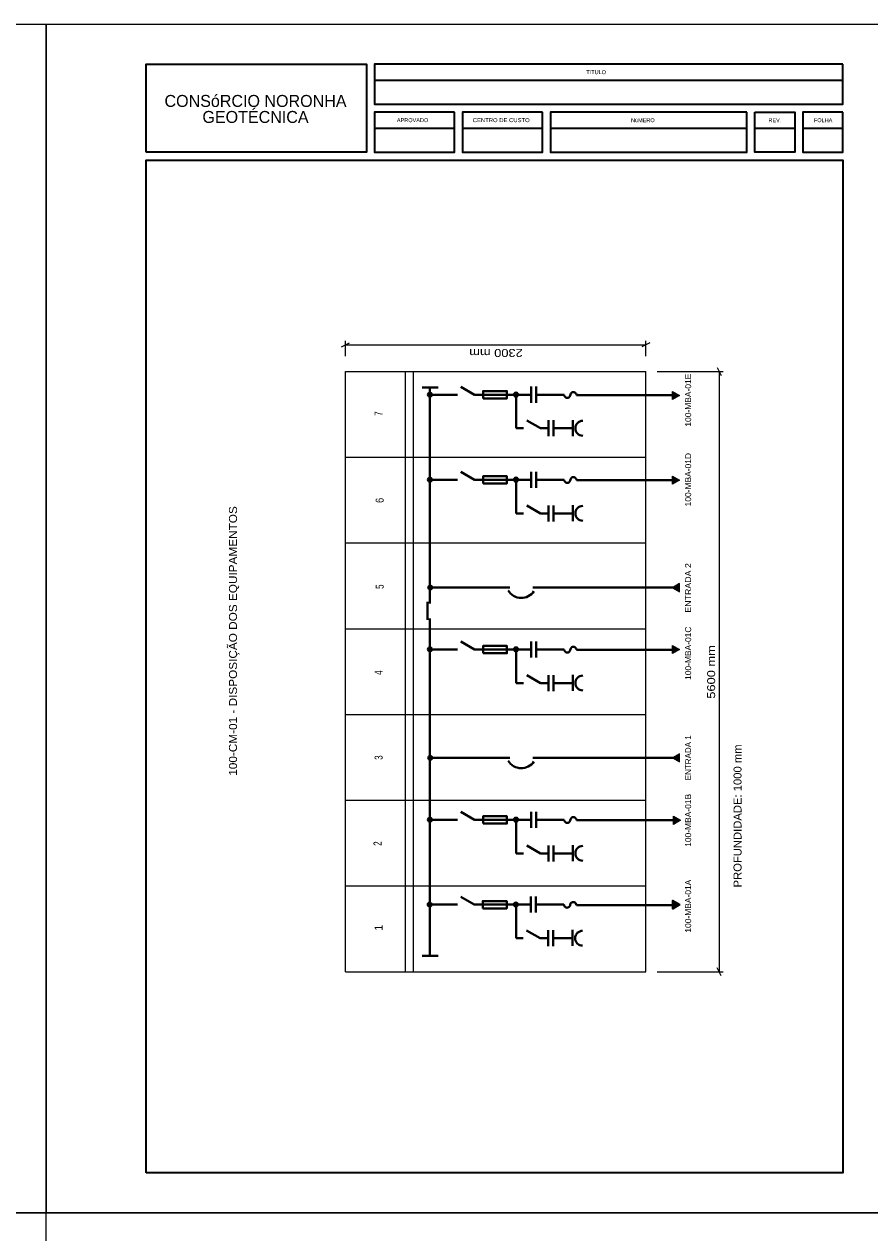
# Model space of a CAD drawing. Extents: x -4160 to -2690, y -474 to 714.
# Drawn here: x -3115.3 to -2904, y 412.5 to 714.5 of the extents above; entities that cross this region are included whole.
import ezdxf
from ezdxf.enums import TextEntityAlignment as Align

# ---------------------------------------------------------------- set-up
doc = ezdxf.new("R2010")
doc.units = 0
doc.header["$LTSCALE"] = 0.56
doc.layers.add('5', color=7, linetype='Continuous', lineweight=35)

msp = doc.modelspace()

# ---------------------------------------------------------------- hatches: boundary and pattern name
at = {"layer": '5'}
for points in [[(-3013.9181, 622.4181, 1), (-3013.9181, 621.4181, 1)], [(-2992.4004, 622.4181, 1), (-2992.4004, 621.4181, 1)], [(-2951.5592, 621.706), (-2953.3121, 620.694), (-2953.3121, 622.718)], [(-3013.9181, 601.1728, 1), (-3013.9181, 600.1728, 1)], [(-2992.4004, 601.1728, 1), (-2992.4004, 600.1728, 1)], [(-2951.5592, 600.5456), (-2953.3121, 599.5336), (-2953.3121, 601.5576)], [(-3013.8436, 574.2158, 1), (-3013.8436, 573.2158, 1)], [(-2953.3234, 573.6788), (-2951.5705, 572.6668), (-2951.5705, 574.6908)], [(-3013.9181, 558.7673, 1), (-3013.9181, 557.7673, 1)], [(-2992.4004, 558.7673, 1), (-2992.4004, 557.7673, 1)], [(-2951.5593, 558.2133), (-2953.3122, 557.2013), (-2953.3122, 559.2253)], [(-3013.8436, 531.6615, 1), (-3013.8436, 530.6615, 1)], [(-2953.315, 531.1744), (-2951.5621, 530.1624), (-2951.5621, 532.1864)], [(-2951.3339, 515.5545), (-2953.0868, 514.5425), (-2953.0868, 516.5665)], [(-3013.9181, 516.213, 1), (-3013.9181, 515.213, 1)], [(-3013.9181, 516.2094, 1), (-3013.9181, 515.2166, 1)], [(-2992.4004, 516.213, 1), (-2992.4004, 515.213, 1)], [(-2951.4563, 494.4858), (-2953.2092, 493.4738), (-2953.2092, 495.4978)], [(-3013.9648, 495.0045, 1), (-3013.9648, 494.0045, 1)], [(-2992.4471, 495.0045, 1), (-2992.4471, 494.0045, 1)]]:
    msp.add_hatch(color=256, dxfattribs=at).paths.add_polyline_path(points)

# ---------------------------------------------------------------- linework, layer by layer
at = {"layer": '5', "lineweight": 25}
for p, q in [((-3109.7642, 417.48), (-3109.7642, 714.48)), ((-3109.7642, 714.48), (-3109.7642, 417.48)), ((-3035.9935, 633.8299), (-3033.9935, 634.8299)), ((-3034.9935, 631.5442), (-3034.9935, 635.3299)), ((-3034.9935, 634.3299), (-2959.9935, 634.3299)), ((-2958.9935, 634.8299), (-2960.9935, 633.8299)), ((-2959.9935, 631.5442), (-2959.9935, 635.3299)), ((-2942.1569, 628.7154), (-2941.1569, 626.7154)), ((-3034.9935, 477.7154), (-3034.9935, 627.7154)), ((-3034.9935, 627.7154), (-2959.9935, 627.7154)), ((-3019.9935, 477.7154), (-3019.9935, 627.7154)), ((-3017.9935, 477.7154), (-3017.9935, 627.7154)), ((-2959.9935, 477.7154), (-2959.9935, 627.7154)), ((-2957.1397, 627.7154), (-2940.6569, 627.7154)), ((-2941.6569, 627.7154), (-2941.6569, 477.7154)), ((-3034.9935, 606.2868), (-2959.9935, 606.2868)), ((-3034.9935, 584.8582), (-2959.9935, 584.8582)), ((-3034.9935, 563.4296), (-2959.9935, 563.4296)), ((-3034.9935, 542.0011), (-2959.9935, 542.0011)), ((-3034.9935, 520.5725), (-2959.9935, 520.5725)), ((-3034.9935, 499.1439), (-2959.9935, 499.1439)), ((-3034.9935, 477.7154), (-2959.9935, 477.7154)), ((-2957.1397, 477.7154), (-2940.6569, 477.7154)), ((-2941.1569, 476.7154), (-2942.1569, 478.7154)), ((-3319.7642, 417.48), (-3109.7642, 417.48))]:
    msp.add_line(p, q, dxfattribs=at)
at = {"layer": '5'}
for p, q in [((-3027.7642, 700.48), (-2910.7642, 700.48)), ((-3027.7642, 688.48), (-3007.7642, 688.48)), ((-3005.7642, 688.48), (-2985.7642, 688.48)), ((-2983.7642, 688.48), (-2934.7642, 688.48)), ((-2932.7642, 688.48), (-2922.7642, 688.48)), ((-2920.7642, 688.48), (-2910.7642, 688.48))]:
    msp.add_line(p, q, dxfattribs=at)
at = {"layer": '5', "lineweight": 40}
for p, q in [((-3015.8797, 623.7284), (-3011.8797, 623.7284)), ((-3013.9648, 569.7636), (-3013.9648, 623.738)), ((-3002.7726, 621.9058), (-3006.1501, 623.8558)), ((-2988.6427, 619.9065), (-2988.6427, 623.9065)), ((-2987.3789, 619.9065), (-2987.3789, 623.9065)), ((-3013.9803, 621.9058), (-3006.9803, 621.9058)), ((-3002.7726, 621.9058), (-2988.6427, 621.9058)), ((-2987.3789, 621.9065), (-2980.3789, 621.9065)), ((-2977.2827, 621.7691), (-2952.982, 621.7691)), ((-2992.3273, 613.4991), (-2990.5269, 613.4991)), ((-2986.3192, 613.4991), (-2989.6967, 615.4491)), ((-2986.3192, 613.4991), (-2984.3242, 613.4991)), ((-2986.3192, 613.4991), (-2984.7328, 613.4991)), ((-2984.3242, 611.4998), (-2984.3242, 615.4998)), ((-2983.0604, 611.4998), (-2983.0604, 615.4998)), ((-2983.0604, 613.4998), (-2978.3525, 613.4998)), ((-2978.2189, 611.5742), (-2978.2189, 615.5742)), ((-3002.7726, 600.6605), (-3006.1501, 602.6105)), ((-2988.6427, 598.6612), (-2988.6427, 602.6612)), ((-2987.3789, 598.6612), (-2987.3789, 602.6612)), ((-3013.9803, 600.6605), (-3006.9803, 600.6605)), ((-3002.7726, 600.6605), (-2988.6427, 600.6605)), ((-2987.3789, 600.6612), (-2980.3789, 600.6612)), ((-2977.2827, 600.5238), (-2952.2827, 600.5238)), ((-2992.3273, 592.2538), (-2990.5269, 592.2538)), ((-2986.3192, 592.2538), (-2989.6967, 594.2038)), ((-2986.3192, 592.2538), (-2984.3242, 592.2538)), ((-2986.3192, 592.2538), (-2984.7328, 592.2538)), ((-2984.3242, 590.2545), (-2984.3242, 594.2545)), ((-2983.0604, 590.2545), (-2983.0604, 594.2545)), ((-2983.0604, 592.2545), (-2978.3525, 592.2545)), ((-2978.2189, 590.3289), (-2978.2189, 594.3289)), ((-3013.9648, 573.6975), (-2993.9648, 573.6975)), ((-2988.2031, 573.6975), (-2952.4454, 573.6975)), ((-3014.5203, 565.6803), (-3014.5203, 570.1204)), ((-3013.9648, 481.738), (-3013.9648, 565.9975)), ((-3002.7726, 558.255), (-3006.1501, 560.205)), ((-2988.6427, 556.2557), (-2988.6427, 560.2557)), ((-2987.3789, 556.2557), (-2987.3789, 560.2557)), ((-3013.9803, 558.255), (-3006.9803, 558.255)), ((-3002.7726, 558.255), (-2988.6427, 558.255)), ((-2987.3789, 558.2557), (-2980.3789, 558.2557)), ((-2977.2827, 558.1183), (-2952.2827, 558.1183)), ((-2992.3273, 549.8483), (-2990.5269, 549.8483)), ((-2986.3192, 549.8483), (-2989.6967, 551.7983)), ((-2986.3192, 549.8483), (-2984.3242, 549.8483)), ((-2986.3192, 549.8483), (-2984.7328, 549.8483)), ((-2984.3242, 547.849), (-2984.3242, 551.849)), ((-2983.0604, 547.849), (-2983.0604, 551.849)), ((-2983.0604, 549.849), (-2978.3525, 549.849)), ((-2978.2189, 547.9234), (-2978.2189, 551.9234)), ((-3013.9648, 531.1432), (-2993.9648, 531.1432)), ((-2988.2031, 531.1432), (-2952.4454, 531.1432)), ((-3002.7726, 515.7007), (-3006.1501, 517.6507)), ((-2988.6427, 513.7014), (-2988.6427, 517.7014)), ((-2987.3789, 513.7014), (-2987.3789, 517.7014)), ((-3013.9803, 515.7007), (-3006.9803, 515.7007)), ((-3002.7726, 515.7007), (-2988.6427, 515.7007)), ((-2987.3789, 515.7014), (-2980.3789, 515.7014)), ((-2977.2827, 515.564), (-2952.2827, 515.564)), ((-2986.3192, 507.294), (-2989.6967, 509.244)), ((-2984.3242, 505.2947), (-2984.3242, 509.2947)), ((-2983.0604, 505.2947), (-2983.0604, 509.2947)), ((-2978.2189, 505.3691), (-2978.2189, 509.3691)), ((-2992.3273, 507.294), (-2990.5269, 507.294)), ((-2986.3192, 507.294), (-2984.3242, 507.294)), ((-2986.3192, 507.294), (-2984.7328, 507.294)), ((-2983.0604, 507.2947), (-2978.3525, 507.2947)), ((-3002.8193, 494.4922), (-3006.1968, 496.4422)), ((-2988.6894, 492.4929), (-2988.6894, 496.4929)), ((-2987.4256, 492.4929), (-2987.4256, 496.4929)), ((-3014.027, 494.4922), (-3007.027, 494.4922)), ((-3002.8193, 494.4922), (-2988.6894, 494.4922)), ((-2987.4256, 494.4929), (-2980.4256, 494.4929)), ((-2977.3294, 494.3555), (-2952.3294, 494.3555)), ((-2986.3659, 486.0855), (-2989.7434, 488.0355)), ((-2984.3709, 484.0862), (-2984.3709, 488.0862)), ((-2983.1071, 484.0862), (-2983.1071, 488.0862)), ((-2978.2656, 484.1606), (-2978.2656, 488.1606)), ((-2992.374, 486.0855), (-2990.5736, 486.0855)), ((-2986.3659, 486.0855), (-2984.3709, 486.0855)), ((-2986.3659, 486.0855), (-2984.7795, 486.0855)), ((-2983.1071, 486.0862), (-2978.3992, 486.0862)), ((-3015.8126, 481.7044), (-3011.8126, 481.7044))]:
    msp.add_line(p, q, dxfattribs=at)
at = {"layer": '5', "lineweight": 25}
msp.add_lwpolyline([(-3109.7642, 417.48), (-3319.7642, 417.48), (-3319.7642, 714.48), (-3109.7642, 714.48)], dxfattribs=at)
for points in [[(-2899.7642, 417.48), (-3109.7642, 417.48), (-3109.7642, 714.48), (-2899.7642, 714.48)], [(-2951.5592, 621.706), (-2953.3121, 620.694), (-2953.3121, 622.718)], [(-2951.5592, 600.5456), (-2953.3121, 599.5336), (-2953.3121, 601.5576)], [(-2953.3234, 573.6788), (-2951.5705, 572.6668), (-2951.5705, 574.6908)], [(-2951.5593, 558.2133), (-2953.3122, 557.2013), (-2953.3122, 559.2253)], [(-2953.315, 531.1744), (-2951.5621, 530.1624), (-2951.5621, 532.1864)], [(-2951.3339, 515.5545), (-2953.0868, 514.5425), (-2953.0868, 516.5665)], [(-2899.7642, 120.48), (-3109.7642, 120.48), (-3109.7642, 417.48), (-2899.7642, 417.48)]]:
    msp.add_lwpolyline(points, close=True, dxfattribs=at)
at = {"layer": '5'}
for points in [[(-3084.7642, 682.48), (-3084.7642, 704.48), (-3029.7642, 704.48), (-3029.7642, 682.48)], [(-2910.7642, 704.48), (-3027.7642, 704.48), (-3027.7642, 694.48), (-2910.7642, 694.48)], [(-3007.7642, 692.48), (-3027.7642, 692.48), (-3027.7642, 682.48), (-3007.7642, 682.48)], [(-2985.7642, 692.48), (-3005.7642, 692.48), (-3005.7642, 682.48), (-2985.7642, 682.48)], [(-2934.7642, 692.48), (-2983.7642, 692.48), (-2983.7642, 682.48), (-2934.7642, 682.48)], [(-2932.7642, 692.48), (-2922.7642, 692.48), (-2922.7642, 682.48), (-2932.7642, 682.48)], [(-2910.7642, 692.48), (-2920.7642, 692.48), (-2920.7642, 682.48), (-2910.7642, 682.48)], [(-3084.7642, 427.48), (-3084.7642, 680.48), (-2910.7642, 680.48), (-2910.7642, 427.48)], [(-2951.4563, 494.4858), (-2953.2092, 493.4738), (-2953.2092, 495.4978)]]:
    msp.add_lwpolyline(points, close=True, dxfattribs=at)
at = {"layer": '5', "lineweight": 40}
for points in [[(-3000.6487, 620.9588), (-3000.6487, 622.7828), (-2994.6808, 622.7828), (-2994.6808, 620.9588)], [(-3000.6487, 599.7135), (-3000.6487, 601.5375), (-2994.6808, 601.5375), (-2994.6808, 599.7135)], [(-3000.6487, 557.308), (-3000.6487, 559.132), (-2994.6808, 559.132), (-2994.6808, 557.308)], [(-3000.6487, 514.7537), (-3000.6487, 516.5777), (-2994.6808, 516.5777), (-2994.6808, 514.7537)], [(-3000.6954, 493.5452), (-3000.6954, 495.3692), (-2994.7275, 495.3692), (-2994.7275, 493.5452)]]:
    msp.add_lwpolyline(points, close=True, dxfattribs=at)
for points in [[(-2992.3273, 613.4991), (-2992.3273, 621.9058), (-2992.3273, 621.9058), (-2992.3273, 621.9181)], [(-2992.3273, 592.2538), (-2992.3273, 600.6605), (-2992.3273, 600.6605), (-2992.3273, 600.6728)], [(-2992.3273, 549.8483), (-2992.3273, 558.255), (-2992.3273, 558.255), (-2992.3273, 558.2673)], [(-2992.3273, 507.294), (-2992.3273, 515.7007), (-2992.3273, 515.7007), (-2992.3273, 515.713)], [(-2992.374, 486.0855), (-2992.374, 494.4922), (-2992.374, 494.4922), (-2992.374, 494.5045)]]:
    msp.add_lwpolyline(points, dxfattribs=at)
for centre, radius in [((-3013.9181, 621.9181), 0.5), ((-2992.4004, 621.9181), 0.5), ((-3013.9181, 600.6728), 0.5), ((-2992.4004, 600.6728), 0.5), ((-3013.8436, 573.7158), 0.5), ((-3013.9181, 558.2673), 0.5), ((-2992.4004, 558.2673), 0.5), ((-3013.8436, 531.1615), 0.5), ((-3013.9181, 515.713), 0.5), ((-3013.9181, 515.713), 0.4964), ((-2992.4004, 515.713), 0.5), ((-3013.9648, 494.5045), 0.5), ((-2992.4471, 494.5045), 0.5)]:
    msp.add_circle(centre, radius, dxfattribs=at)
for centre, radius, start, end in [((-2978.0585, 621.7698), 0.7758, 359.9483, 180), ((-2979.6031, 621.9058), 0.7758, 179.9483, 0), ((-2975.7224, 613.5114), 1.8599, 90, 270), ((-2978.0585, 600.5245), 0.7758, 359.9483, 180), ((-2979.6031, 600.6605), 0.7758, 179.9483, 0), ((-2975.7224, 592.2661), 1.8599, 90, 270), ((-2991.069, 574.9606), 3.8414, 211.55542, 325.35427), ((-2978.0585, 558.119), 0.7758, 359.9483, 180), ((-2979.6031, 558.255), 0.7758, 179.9483, 0), ((-2975.7224, 549.8606), 1.8599, 90, 270), ((-2991.069, 532.4063), 3.8414, 211.55542, 325.35427), ((-2979.6031, 515.7007), 0.7758, 179.9483, 0), ((-2978.0585, 515.5647), 0.7758, 359.9483, 180), ((-2975.7224, 507.3063), 1.8599, 90, 270), ((-2979.6498, 494.4922), 0.7758, 179.9483, 0), ((-2978.1052, 494.3562), 0.7758, 359.9483, 180), ((-2975.7691, 486.0978), 1.8599, 90, 270)]:
    msp.add_arc(centre, radius, start, end, dxfattribs=at)

# ---------------------------------------------------------------- texts
at = {"layer": '5'}
for s, height, p in [('TíTULO', 1, (-2972.3847, 701.991)), ('CONSóRCIO NORONHA', 3, (-3057.4749, 693.7961)), ('GEOTÉCNICA', 3, (-3057.475, 689.7961)), ('APROVADO', 1, (-3018.2387, 689.9973)), ('REV.', 1, (-2927.7443, 689.9923)), ('FOLHA', 1, (-2915.6809, 689.9923))]:
    msp.add_text(s, height=height, dxfattribs=at).set_placement(p, align=Align.CENTER)
for s, width, p in [('CENTRO DE CUSTO', 1.1, (-2996.0934, 689.9973)), ('NúMERO', 0.95, (-2960.7228, 689.9923))]:
    msp.add_text(s, height=1, dxfattribs=dict(at, width=width)).set_placement(p, align=Align.CENTER)
for s, height, rotation, width, p in [('2300 mm', 2, 180, 1.2, (-2990.7143, 633.33)), ('100-MBA-01E', 1.5, 90, 1.05, (-2948.6523, 613.9159)), ('7', 2, 90, 0.75, (-3025.7315, 616.6033)), ('100-MBA-01D', 1.5, 90, 1.05, (-2948.6523, 593.9927)), ('6', 2, 90, 0.85, (-3025.4628, 594.8516)), ('100-CM-01 - DISPOSIÇÃO DOS EQUIPAMENTOS', 2, 90, 1.1, (-3062.1034, 526.6868)), ('ENTRADA 2', 1.5, 90, 1.1, (-2948.6523, 567.4314)), ('5', 2, 90, 0.75, (-3025.4628, 573.3684)), ('100-MBA-01C', 1.5, 90, 1.05, (-2948.6523, 550.6219)), ('5600 mm', 2, 90, 1.2, (-2942.6569, 545.9362)), ('4', 2, 90, 0.75, (-3025.7315, 551.8852)), ('3', 2, 90, 0.75, (-3025.7315, 530.6706)), ('PROFUNDIDADE: 1000 mm', 2, 90, 1.05, (-2936.0651, 498.7793)), ('100-MBA-01B', 1.5, 90, 1.05, (-2948.6523, 508.9329)), ('2', 2, 90, 0.75, (-3026.0003, 509.1874)), ('100-MBA-01A', 1.5, 90, 1.05, (-2948.6523, 487.4827))]:
    msp.add_text(s, height=height, rotation=rotation, dxfattribs=dict(at, width=width)).set_placement(p)
for s, height, p in [('ENTRADA 1', 1.5, (-2948.6523, 525.5451)), ('1', 2, (-3025.7315, 487.9728))]:
    msp.add_text(s, height=height, rotation=90, dxfattribs=at).set_placement(p)

doc.saveas('drawing.dxf')
